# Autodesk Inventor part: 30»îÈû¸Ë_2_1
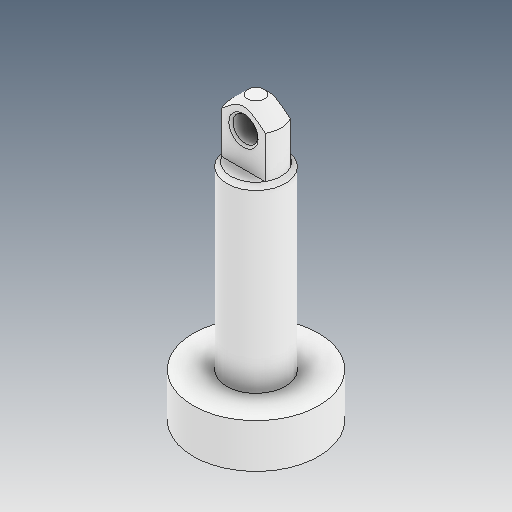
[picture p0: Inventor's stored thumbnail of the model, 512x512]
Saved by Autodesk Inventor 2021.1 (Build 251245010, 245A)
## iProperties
Created: 2021-05
Part Number: 30»îÈû¸Ë_2_1
Material: Ogólny
Document SubType Name: Modeling
Designer: user
Density: 1 g/cm^3
Appearance: Domyślna
Author: user
Revision Number: ÈÎºÎ
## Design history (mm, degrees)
feature "ÊäÈë1"
node "Bryła1"
